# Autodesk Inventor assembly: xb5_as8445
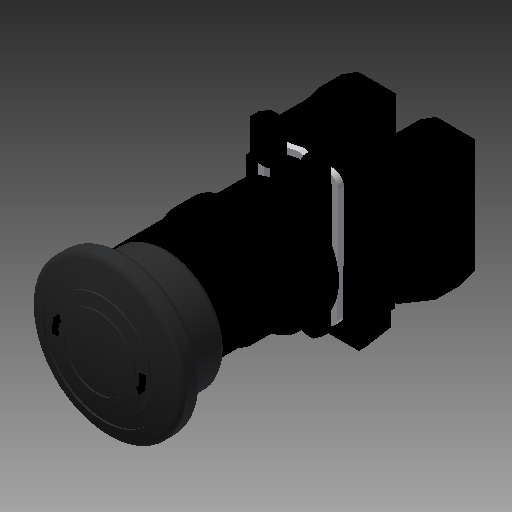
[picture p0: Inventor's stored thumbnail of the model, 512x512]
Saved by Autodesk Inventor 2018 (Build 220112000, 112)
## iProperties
Company: TraceParts S.A.
Created: 2018-04
Part Number: xb5_as8445
Checked By: TraceParts S.A.
Catalog Web Link: www.traceparts.com
Document SubType Name: Assembly
Designer: TraceParts
REFERENCE: XB5 AS8445
DESIGN: Unité de commande et de signalisation Ø 22 Harmony XB5 plastique - Boutons-poussoirs coup de poing à accrochage - Arrêt d'urgence à verrouillage brusque à accro
SUPPLIER: Schneider Electric
TraceParts.PartNumber: 10-29052009-106837
TraceParts.PartTitle: Unité de commande et de signalisation Ø 22 Harmony XB5 plastique - Boutons-poussoirs coup de poing à accrochage - Arrêt d'urgence à verrouillage brusque à accro
TraceParts.InstanceId: 10-29052009-106837DJSZYM31C3QMKZY0IA7L6YWZG
TraceParts.PartStatus: Published
TraceParts.PartVersion: 1.1.5
TRACEPARTS: TRACEPARTS
TraceParts.PartLanguage: fr
TraceParts.ClassPath: SCHNEIDER_ELECTRIC:/F_SCHNEIDER/F_TELEMECANIQUE/F_TELEMECANIQUE.04/F_TELEMECANIQUE.04.010/F_TELEMECANIQUE.04.010.020/10-29052009-106837
Author: TraceParts
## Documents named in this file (13)
- D:\01 Paralaia\Grupos de Traballo\GT Maquetas\CAD 3D\Botoneras Schneider\Seta XB5AS8445\xb5_as8445.iam
- D:\01 Paralaia\Grupos de Traballo\GT Maquetas\CAD 3D\Botoneras Schneider\Seta XB5AS8445\xb5_as8445_01.ipt
- D:\01 Paralaia\Grupos de Traballo\GT Maquetas\CAD 3D\Botoneras Schneider\Seta XB5AS8445\xb5_as8445_02.ipt
- D:\01 Paralaia\Grupos de Traballo\GT Maquetas\CAD 3D\Botoneras Schneider\Seta XB5AS8445\xb5_as8445_03.ipt
- D:\01 Paralaia\Grupos de Traballo\GT Maquetas\CAD 3D\Botoneras Schneider\Seta XB5AS8445\xb5_as8445_04.ipt
- D:\01 Paralaia\Grupos de Traballo\GT Maquetas\CAD 3D\Botoneras Schneider\Seta XB5AS8445\xb5_as8445_05.ipt
- D:\01 Paralaia\Grupos de Traballo\GT Maquetas\CAD 3D\Botoneras Schneider\Seta XB5AS8445\xb5_as8445_06.ipt
- D:\01 Paralaia\Grupos de Traballo\GT Maquetas\CAD 3D\Botoneras Schneider\Seta XB5AS8445\xb5_as8445_07.ipt
- D:\01 Paralaia\Grupos de Traballo\GT Maquetas\CAD 3D\Botoneras Schneider\Seta XB5AS8445\xb5_as8445_08.ipt
- D:\01 Paralaia\Grupos de Traballo\GT Maquetas\CAD 3D\Botoneras Schneider\Seta XB5AS8445\xb5_as8445_09.ipt
- D:\01 Paralaia\Grupos de Traballo\GT Maquetas\CAD 3D\Botoneras Schneider\Seta XB5AS8445\xb5_as8445_10.ipt
- D:\01 Paralaia\Grupos de Traballo\GT Maquetas\CAD 3D\Botoneras Schneider\Seta XB5AS8445\xb5_as8445_11.ipt
- D:\01 Paralaia\Grupos de Traballo\GT Maquetas\CAD 3D\Botoneras Schneider\Seta XB5AS8445\xb5_as8445_12.ipt
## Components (12 placed, 12 different names)
1. xb5_as8445_01:1
2. xb5_as8445_02:1
3. xb5_as8445_03:1
4. xb5_as8445_04:1
5. xb5_as8445_05:1
6. xb5_as8445_06:1
7. xb5_as8445_07:1
8. xb5_as8445_08:1
9. xb5_as8445_09:1
10. xb5_as8445_10:1
11. xb5_as8445_11:1
12. xb5_as8445_12:1
